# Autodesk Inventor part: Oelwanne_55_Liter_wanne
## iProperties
Created: 2005-05
Part Number: Oelwanne_55_Liter_wanne
Document SubType Name: Sheet Metal
Designer: Mario Wipf
Manufacturer: Standard
Standards Organization: Custom
Author: Mario Wipf
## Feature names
1. Extrusion1
2. Grobblech1
3. Grobblech2
4. Biegung1
5. Grobblech3
6. Biegung2
7. Grobblech4
8. Biegung3
9. Grobblech5
10. Biegung4
